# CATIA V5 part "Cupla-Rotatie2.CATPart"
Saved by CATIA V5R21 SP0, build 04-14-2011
Part number: Cupla R2
Bounding box of the stored display mesh (mm): x -110 to 100, y -100 to 100, z 0 to 660
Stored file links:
  C:\Users\MIRCEA\Desktop\PRRO\CATIAV5\Cupla-Rotatie2.CATPart
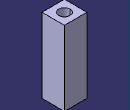
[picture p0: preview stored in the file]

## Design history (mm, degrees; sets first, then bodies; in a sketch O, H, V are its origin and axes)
AxisSystem1: origin (0, 0, 0), X (1, 0, 0), Y (0, 1, 0), Z (0, 0, 1)
Body1 (main body)
  Sketch1 on xy-plane, origin (0, 0, 0), H (1, 0, 0), V (0, 1, 0)
    circle A1 centre (0, 0) radius 50
    line L1 (100, 100) -> (100, -100)
    line L2 (100, -100) -> (-100, -100)
    line L3 (-100, -100) -> (-100, 100)
    line L4 (-100, 100) -> (100, 100)
    radius A1 = 50
    distance L2 L4 = 200
    distance L1 L3 = 200
    vertical: L1 V, L3 V
    horizontal: L2 H, L4 H
    equidistance: L1 L3 O, L2 L4 O
  Pad1: profile Sketch1, direction (0, 0, 1), length 660
  Plane1: type Offset, RefPlane yz-plane, Offset -100
  Sketch2 on Plane1, origin (-100, 0, 0), H (0, 1, 0), V (0, 0, 1)
    point P1 (0, 330)
    line L1 (75, 405) -> (75, 255)
    line L2 (75, 255) -> (-75, 255)
    line L3 (-75, 255) -> (-75, 405)
    line L4 (-75, 405) -> (75, 405)
    distance L2 L4 = 150
    distance L1 L3 = 150
    vertical: L1 V, L3 V
    horizontal: L2 H, L4 H
    equidistance: L1 L3 P1, L2 L4 P1
  Pad2: profile Sketch2, direction (-1, 0, 0), length 10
